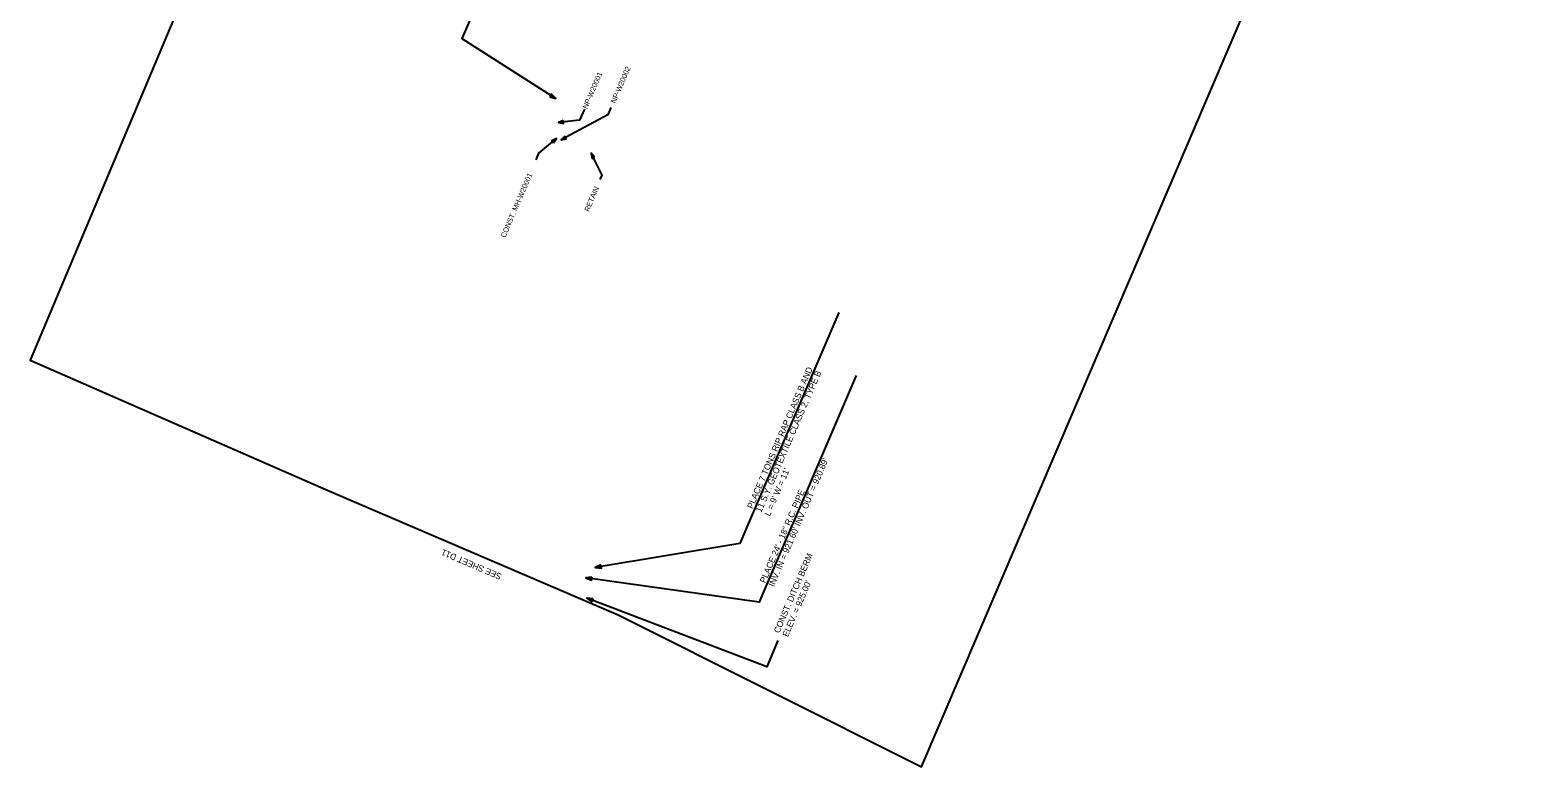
# Model space of a CAD drawing. Extents: x 1615213 to 1616738, y 1098243 to 1100099.
# Drawn here: x 1615213 to 1616663, y 1098243 to 1098952 of the extents above; entities that cross this region are included whole.
import ezdxf

# ---------------------------------------------------------------- set-up
doc = ezdxf.new("R2010")
doc.units = 0
for name, color, linetype in [('Plan_Clip', 7, 'Continuous'), ('RD_SHT_MatchLine', 7, 'Continuous'), ('RD_TX_Drainage', 7, 'Continuous')]:
    doc.layers.add(name, color=color, linetype=linetype)

msp = doc.modelspace()

# ---------------------------------------------------------------- linework, layer by layer
at = {"layer": 'Plan_Clip'}
msp.add_lwpolyline([(1615502.7, 1098507.9), (1615778.5, 1098389.7), (1616070.1, 1098243.5), (1616662.9, 1099630.3), (1616368.7, 1099765.8), (1616095.1, 1099888.9), (1615829.5, 1100008.4), (1615766.4, 1099858.4), (1615733.7, 1099872.1), (1615213.1, 1098634.6)], close=True, dxfattribs=at)
msp.add_lwpolyline([(1615502.7, 1098507.9), (1615778.5, 1098389.7), (1616070.1, 1098243.5), (1616662.9, 1099630.3), (1616368.7, 1099765.8), (1616095.1, 1099888.9), (1615829.5, 1100008.4), (1615766.4, 1099858.4), (1615733.7, 1099872.1), (1615213.1, 1098634.6)], close=True, dxfattribs=at)
msp.add_lwpolyline([(1615502.7, 1098507.9), (1615778.5, 1098389.7), (1616070.1, 1098243.5), (1616662.9, 1099630.3), (1616368.7, 1099765.8), (1616095.1, 1099888.9), (1615829.5, 1100008.4), (1615766.4, 1099858.4), (1615733.7, 1099872.1), (1615213.1, 1098634.6)], close=True, dxfattribs=at)
msp.add_lwpolyline([(1615502.7, 1098507.9), (1615778.5, 1098389.7), (1616070.1, 1098243.5), (1616662.9, 1099630.3), (1616368.7, 1099765.8), (1616095.1, 1099888.9), (1615829.5, 1100008.4), (1615766.4, 1099858.4), (1615733.7, 1099872.1), (1615213.1, 1098634.6)], close=True, dxfattribs=at)
msp.add_lwpolyline([(1615502.7, 1098507.9), (1615778.5, 1098389.7), (1616070.1, 1098243.5), (1616662.9, 1099630.3), (1616368.7, 1099765.8), (1616095.1, 1099888.9), (1615829.5, 1100008.4), (1615766.4, 1099858.4), (1615733.7, 1099872.1), (1615213.1, 1098634.6)], close=True, dxfattribs=at)
msp.add_lwpolyline([(1615502.7, 1098507.9), (1615778.5, 1098389.7), (1616070.1, 1098243.5), (1616662.9, 1099630.3), (1616368.7, 1099765.8), (1616095.1, 1099888.9), (1615829.5, 1100008.4), (1615766.4, 1099858.4), (1615733.7, 1099872.1), (1615213.1, 1098634.6)], close=True, dxfattribs=at)
at = {"layer": 'RD_TX_Drainage'}
for p, q in [((1615715.7, 1099147.9), (1615631.7, 1098952)), ((1615990.7, 1098680.5), (1615906.7, 1098484.7)), ((1616007.5, 1098619.8), (1615918.2, 1098411.8))]:
    msp.add_line(p, q, dxfattribs=at)
for points in [[(1615631.7, 1098952), (1615628.2, 1098944), (1615718.5, 1098886.2)], [(1615746, 1098875.9), (1615741.5, 1098865.5), (1615721, 1098863.2)], [(1615771.5, 1098877.6), (1615768.5, 1098870.5), (1615723.6, 1098846.5)], [(1615699.7, 1098827.4), (1615702.4, 1098833.8), (1615719.2, 1098847.8)], [(1615761.1, 1098808.3), (1615763, 1098812.6), (1615752.5, 1098833.6)], [(1615906.7, 1098484.7), (1615895.4, 1098458.3), (1615756.4, 1098435.3)], [(1615918.2, 1098411.8), (1615914.1, 1098402), (1615747.3, 1098425.2)], [(1615932.2, 1098364.9), (1615921.4, 1098339.6), (1615748.4, 1098405.6)]]:
    msp.add_lwpolyline(points, dxfattribs=at)
for points in [[(1615712.8, 1098888), (1615718.5, 1098886.2), (1615714.4, 1098890.6)], [(1615725.7, 1098865), (1615721, 1098863.2), (1615726, 1098862.4)], [(1615727.3, 1098849.9), (1615723.6, 1098846.5), (1615728.5, 1098847.6)], [(1615716.3, 1098843.7), (1615719.2, 1098847.8), (1615714.6, 1098845.7)], [(1615755.8, 1098829.9), (1615752.5, 1098833.6), (1615753.5, 1098828.7)], [(1615761.9, 1098437.8), (1615756.4, 1098435.3), (1615762.4, 1098434.7)], [(1615753.3, 1098426), (1615747.3, 1098425.2), (1615752.8, 1098422.9)], [(1615754.4, 1098405), (1615748.4, 1098405.6), (1615753.2, 1098402.1)]]:
    msp.add_lwpolyline(points, close=True, dxfattribs=at)

# ---------------------------------------------------------------- texts
at = {"layer": 'RD_SHT_MatchLine'}
msp.add_text('SEE SHEET D11', height=6, rotation=156.8359, dxfattribs=at).set_placement((1615667.1, 1098428.7))
at = {"layer": 'RD_TX_Drainage'}
for s, height, p in [('NP-W20001', 5, (1615748.7, 1098875.9)), ('NP-W20002', 5, (1615775.8, 1098881.2)), ('CONST. MH-W20001', 5, (1615670, 1098752)), ('RETAIN', 5, (1615750.4, 1098777)), ('PLACE 7 TONS RIP RAP CLASS B AND', 6, (1615907.8, 1098491.2)), ('11 S.Y. GEOTEXTILE CLASS 2, TYPE B', 6, (1615916.1, 1098487.6)), ("L = 9' W = 11'", 6, (1615924.4, 1098484.1)), ("INV. IN = 921.60' INV. OUT = 920.89'", 6, (1615928.3, 1098416.2)), ('PLACE 24\' - 18" R.C. PIPE', 6, (1615920, 1098419.7)), ('CONST. DITCH BERM', 6, (1615933.4, 1098371.5)), ("ELEV. = 925.00'", 6, (1615941.7, 1098367.9))]:
    msp.add_text(s, height=height, rotation=66.7846, dxfattribs=at).set_placement(p)

doc.saveas('drawing.dxf')
